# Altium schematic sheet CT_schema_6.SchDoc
size 368 x 245 mm
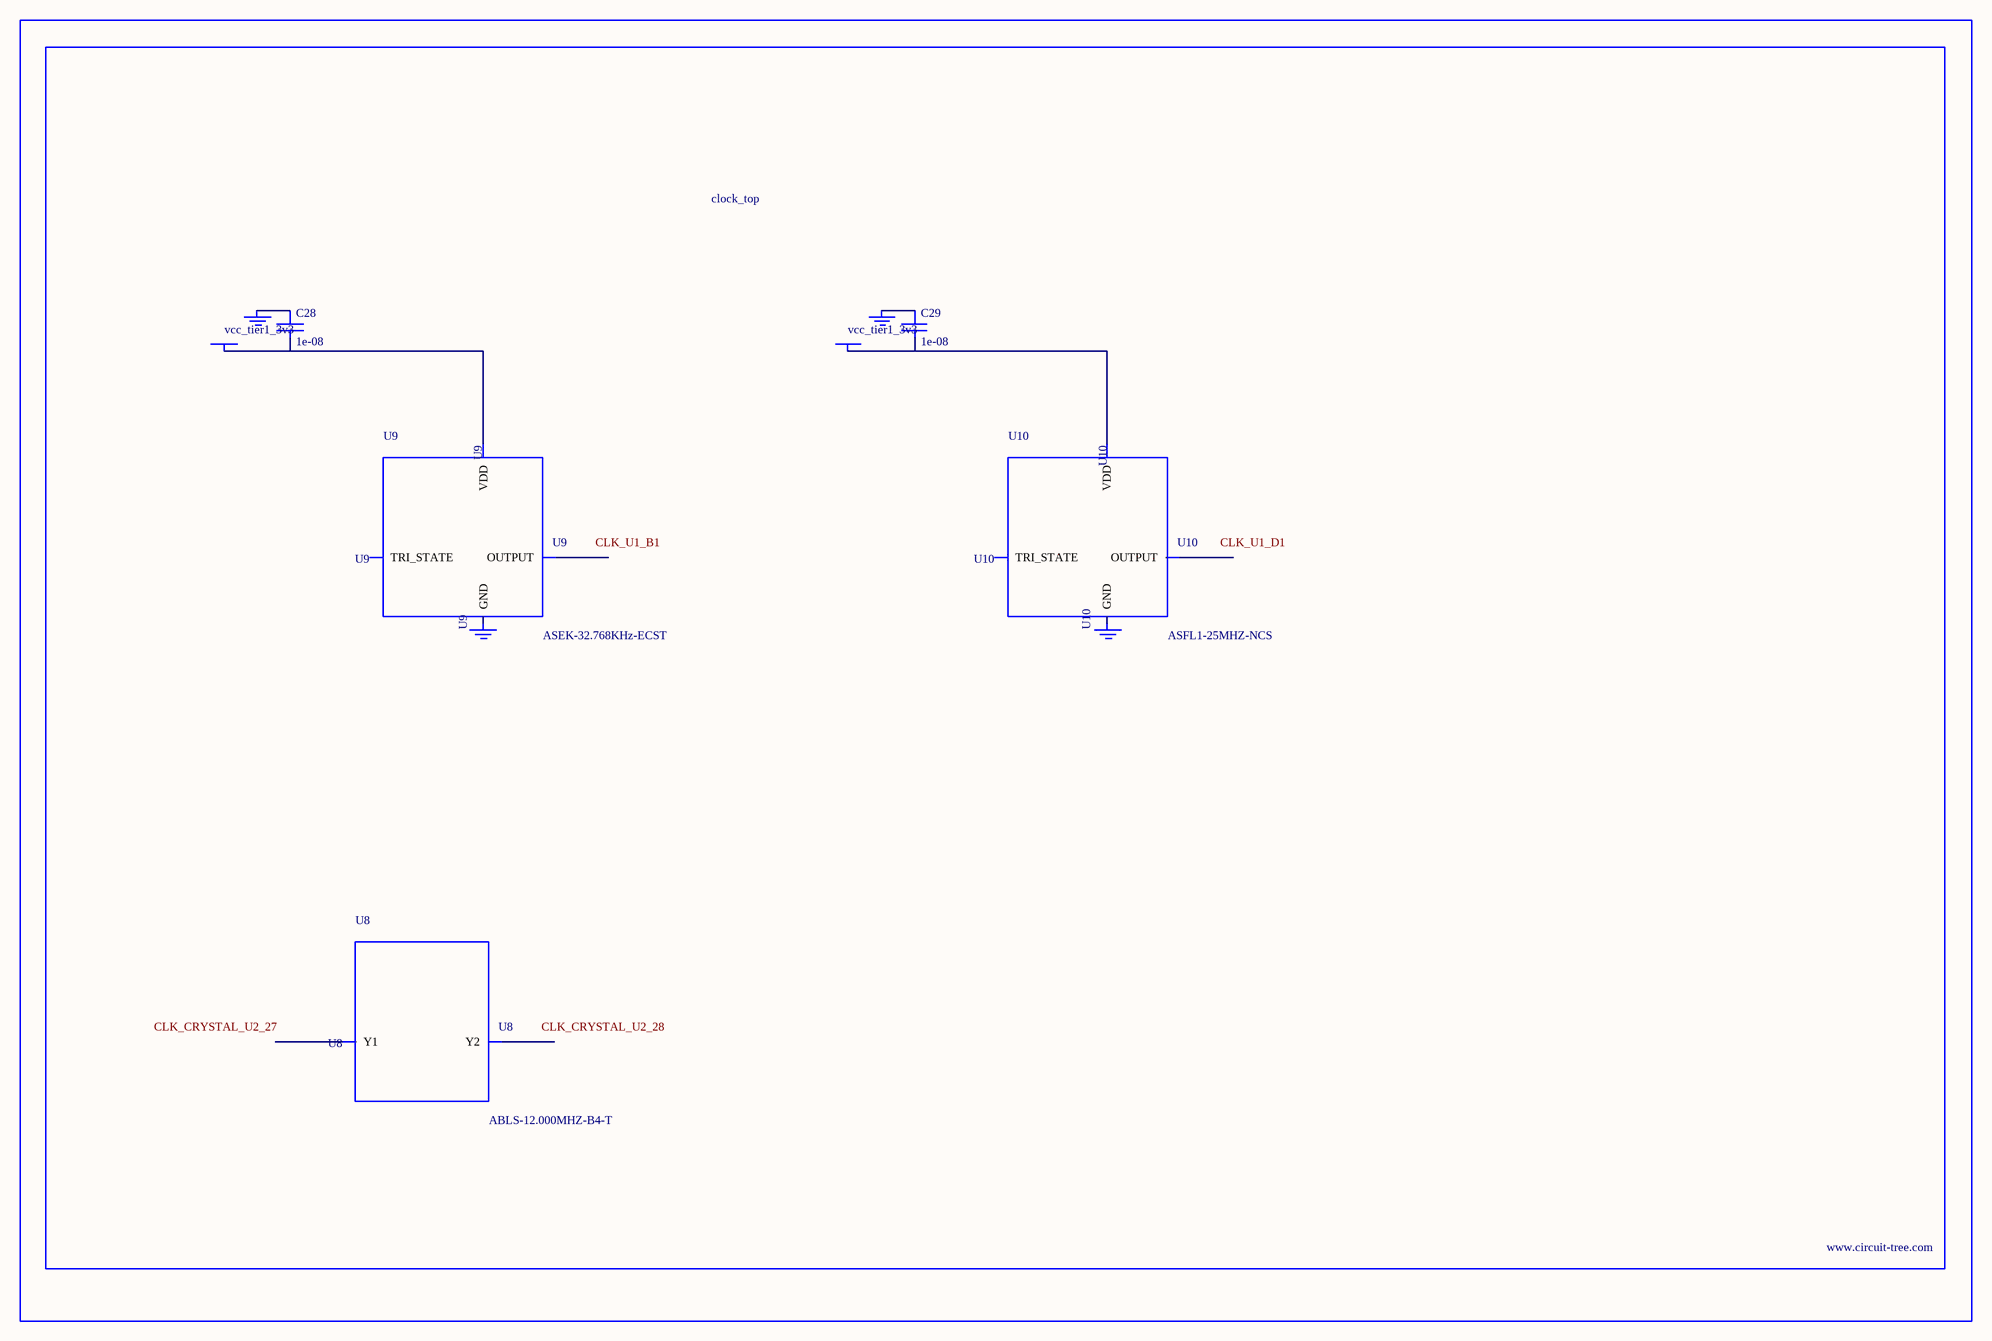
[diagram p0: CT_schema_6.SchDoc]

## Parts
BORDER5  (no value)
C28  1e-08  [C0402]
C29  1e-08  [C0402]
GND_INSTANCE_5_0  (no value)
GND_INSTANCE_5_1  (no value)
GND_INSTANCE_5_2  (no value)
GND_INSTANCE_5_3  (no value)
POWER_INSTANCE_5_0  vcc_tier1_3v3
POWER_INSTANCE_5_1  vcc_tier1_3v3
U8  ABLS-12.000MHZ-B4-T  [ABLS-12.000MHZ-B4-T]
U9  ASEK-32.768KHz-ECST  [ASEK]
U10  ASFL1-25MHZ-NCS  [ASFL1]

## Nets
NetC28_1: C28.1 GND_INSTANCE_5_0.0(GND)
NetC28_2: C28.2 POWER_INSTANCE_5_0.0(PWR) U9.4(VDD)
NetC29_1: C29.1 GND_INSTANCE_5_2.0(GND)
NetC29_2: C29.2 POWER_INSTANCE_5_1.0(PWR) U10.4(VDD)

Not connected (* = marked no-connect by the designer): GND_INSTANCE_5_1 0(GND); GND_INSTANCE_5_3 0(GND); U8 1(Y1) 2(Y2); U9 1(TRI_STATE) 2(GND) 3(OUTPUT); U10 1(TRI_STATE) 2(GND) 3(OUTPUT)

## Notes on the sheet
- Labels drawn without touching a wire or pin: CLK_CRYSTAL_U2_27, CLK_CRYSTAL_U2_28, CLK_U1_B1, CLK_U1_D1

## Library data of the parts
BORDER5 = BORDER_PAGE5
C28 C29 = C0402C103K3RAC
GND_INSTANCE_5_0-GND_INSTANCE_5_3 = GND
POWER_INSTANCE_5_0 POWER_INSTANCE_5_1 = PWR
